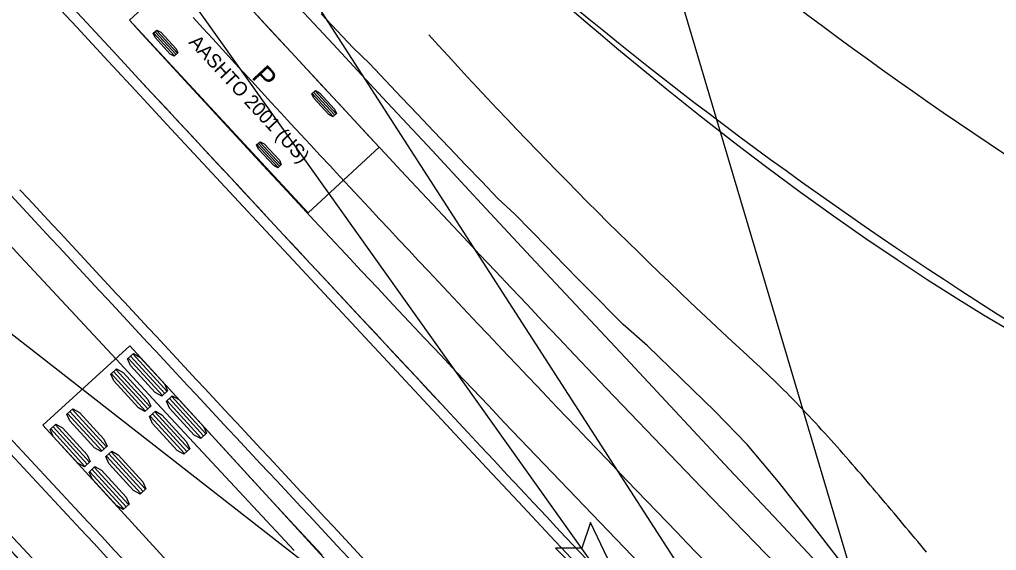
# Model space of a CAD drawing. Extents: x 1262642 to 1268358, y 767825 to 773481.
# Drawn here: x 1266689.1 to 1266759.8, y 772247.4 to 772285.8 of the extents above; entities that cross this region are included whole.
import ezdxf

# ---------------------------------------------------------------- set-up
doc = ezdxf.new("R2010")
doc.units = 0
for name, color, linetype in [('Prop Conc 1ft 6in Curb and Gutter', 7, 'Continuous'), ('Prop Conc 5in Monolithic Keyed In Island', 7, 'Continuous'), ('Prop Dimension Text', 7, 'Continuous'), ('Prop EOT', 7, 'Continuous'), ('Prop Horizontal Alignment', 7, 'Continuous'), ('Prop Lane Lines', 7, 'Continuous'), ('Prop Paved Shoulder', 7, 'Continuous'), ('Prop Shade Light', 7, 'Continuous'), ('Prop Shade Medium', 7, 'Continuous'), ('Prop Terminator CELL', 7, 'Continuous'), ('Scratch_Level_3', 7, 'Continuous')]:
    doc.layers.add(name, color=color, linetype=linetype)

msp = doc.modelspace()

# ---------------------------------------------------------------- linework, layer by layer
at = {"layer": 'Prop Conc 1ft 6in Curb and Gutter'}
for radius, start, end in [(11385.75, 220.9464115, 223.1036607), (11396.75, 222.8296601, 223.1041091)]:
    msp.add_arc((1275047.307, 780021.225), radius, start, end, dxfattribs=at)
at = {"layer": 'Prop Conc 5in Monolithic Keyed In Island'}
for radius, start, end in [(11410.25, 222.8296601, 223.2792706), (11414.25, 222.8297896, 223.4298287)]:
    msp.add_arc((1275047.307, 780021.225), radius, start, end, dxfattribs=at)
at = {"layer": 'Prop Dimension Text'}
for p, q in [((1266734.359, 772241.11), (1266654.367, 772353.573)), ((1266758.201, 772215.712), (1266729.837, 772311.282)), ((1266637.674, 772302.797), (1266726.388, 772233.528)), ((1266758.372, 772212.843), (1266700.467, 772302.683))]:
    msp.add_line(p, q, dxfattribs=at)
at = {"layer": 'Prop EOT'}
for centre, radius, start, end in [((1275047.307, 780021.225), 11385, 220.9464115, 222.9935866), ((1266920.515, 772517.827), 300, 222.71603, 239.6427), ((1275047.307, 780021.225), 11385, 222.8296601, 223.2789723), ((1275047.307, 780021.225), 11397.5, 222.8287756, 223.1041206), ((1275047.307, 780021.225), 11409.5, 222.8296601, 223.2792706), ((1275047.307, 780021.225), 11415, 222.8297896, 223.4298287)]:
    msp.add_arc(centre, radius, start, end, dxfattribs=at)
at = {"layer": 'Prop Horizontal Alignment'}
msp.add_arc((1275047.307, 780021.225), 11400, 216.7663646, 222.9935866, dxfattribs=at)
at = {"layer": 'Prop Lane Lines'}
for radius, start, end in [(11373, 216.3649439, 223.1327476), (11427, 216.3674993, 223.5476842), (11415, 220.9464115, 223.1041206)]:
    msp.add_arc((1275047.307, 780021.225), radius, start, end, dxfattribs=at)
at = {"layer": 'Prop Paved Shoulder'}
for centre, radius, start, end in [((1275047.307, 780021.225), 11449, 220.5050908, 223.2024475), ((1266920.515, 772517.827), 290, 222.71603, 239.65201)]:
    msp.add_arc(centre, radius, start, end, dxfattribs=at)
at = {"layer": 'Prop Shade Light'}
for centre, radius, start, end in [((1275047.307, 780021.225), 11449, 220.5050908, 223.2024475), ((1266920.515, 772517.827), 290, 222.71603, 239.65201), ((1266920.515, 772517.827), 300, 222.71603, 239.6427)]:
    msp.add_arc(centre, radius, start, end, dxfattribs=at)
at = {"layer": 'Prop Shade Medium'}
for radius, start, end in [(11410.25, 222.8296601, 223.2792706), (11414.25, 222.8297896, 223.4298287)]:
    msp.add_arc((1275047.307, 780021.225), radius, start, end, dxfattribs=at)
at = {"layer": 'Prop Terminator CELL'}
msp.add_lwpolyline([(1266727.879, 772247.545), (1266734.359, 772241.11), (1266730.417, 772249.412), (1266729.78, 772247.547)], close=True, dxfattribs=at)
at = {"layer": 'Scratch_Level_3'}
for p, q in [((1266702.231, 772290.506), (1266697.093, 772285.751)), ((1266715.136, 772276.561), (1266702.231, 772290.506)), ((1266697.093, 772285.751), (1266709.998, 772271.806)), ((1266697.093, 772285.751), (1266697.093, 772285.751)), ((1266698.84, 772284.816), (1266700.359, 772283.156)), ((1266698.944, 772284.911), (1266700.463, 772283.251)), ((1266699.048, 772285.006), (1266700.567, 772283.346)), ((1266710.299, 772280.43), (1266711.828, 772278.779)), ((1266710.403, 772280.526), (1266711.931, 772278.874)), ((1266710.506, 772280.621), (1266712.034, 772278.97)), ((1266706.412, 772276.832), (1266707.94, 772275.181)), ((1266706.515, 772276.928), (1266708.043, 772275.277)), ((1266706.309, 772276.737), (1266707.837, 772275.085)), ((1266709.998, 772271.806), (1266715.136, 772276.561)), ((1266697.109, 772262.181), (1266690.837, 772256.444)), ((1266729.506, 772226.762), (1266697.109, 772262.181)), ((1266699.639, 772258.735), (1266697.165, 772261.441)), ((1266699.808, 772258.89), (1266697.334, 772261.595)), ((1266699.47, 772258.581), (1266696.995, 772261.286)), ((1266698.253, 772257.467), (1266695.778, 772260.172)), ((1266698.422, 772257.622), (1266695.947, 772260.327)), ((1266698.591, 772257.776), (1266696.116, 772260.482)), ((1266702.621, 772255.815), (1266700.146, 772258.521)), ((1266702.282, 772255.506), (1266699.808, 772258.212)), ((1266702.451, 772255.661), (1266699.977, 772258.366)), ((1266695.092, 772254.576), (1266692.617, 772257.282)), ((1266695.261, 772254.731), (1266692.786, 772257.436)), ((1266695.43, 772254.885), (1266692.956, 772257.591)), ((1266701.065, 772254.392), (1266698.59, 772257.098)), ((1266701.234, 772254.547), (1266698.759, 772257.253)), ((1266701.403, 772254.702), (1266698.928, 772257.407)), ((1266690.837, 772256.444), (1266723.234, 772221.025)), ((1266694.213, 772253.772), (1266691.738, 772256.477)), ((1266693.875, 772253.462), (1266691.4, 772256.168)), ((1266694.044, 772253.617), (1266691.569, 772256.323)), ((1266698.073, 772251.656), (1266695.599, 772254.362)), ((1266698.243, 772251.811), (1266695.768, 772254.516)), ((1266697.904, 772251.501), (1266695.43, 772254.207)), ((1266696.687, 772250.388), (1266694.212, 772253.093)), ((1266696.856, 772250.543), (1266694.381, 772253.248)), ((1266697.025, 772250.697), (1266694.55, 772253.403))]:
    msp.add_line(p, q, dxfattribs=at)
for points in [[(1266728.117, 772262.745), (1266726.973, 772263.953), (1266725.829, 772265.163), (1266724.686, 772266.373), (1266723.544, 772267.585), (1266722.403, 772268.797), (1266721.263, 772270.011), (1266720.125, 772271.225), (1266718.987, 772272.441), (1266717.85, 772273.657), (1266716.715, 772274.874), (1266715.58, 772276.093), (1266714.446, 772277.312), (1266713.314, 772278.532), (1266712.182, 772279.753), (1266711.051, 772280.975), (1266709.92, 772282.197), (1266708.79, 772283.419), (1266707.659, 772284.641), (1266706.528, 772285.863), (1266705.397, 772287.084), (1266704.266, 772288.306), (1266703.136, 772289.528), (1266702.231, 772290.506)], [(1266741.475, 772276.359), (1266740.75, 772276.916), (1266739.543, 772277.855), (1266738.336, 772278.804), (1266737.131, 772279.764), (1266735.927, 772280.734), (1266734.725, 772281.714), (1266733.525, 772282.703), (1266732.326, 772283.702), (1266731.13, 772284.71), (1266729.93, 772285.73), (1266728.732, 772286.76)], [(1266732.788, 772263.728), (1266732.065, 772264.448), (1266730.865, 772265.651), (1266729.67, 772266.858), (1266728.481, 772268.069), (1266727.298, 772269.285), (1266726.12, 772270.502), (1266724.945, 772271.719), (1266723.723, 772272.841), (1266722.555, 772274.061), (1266721.389, 772275.281), (1266720.226, 772276.501), (1266719.065, 772277.72), (1266717.907, 772278.94), (1266716.75, 772280.159), (1266715.596, 772281.379), (1266714.444, 772282.6), (1266713.252, 772283.753), (1266712.103, 772284.978), (1266710.953, 772286.205)], [(1266723.035, 772257.856), (1266721.886, 772259.069), (1266720.738, 772260.283), (1266719.591, 772261.498), (1266718.446, 772262.714), (1266717.301, 772263.931), (1266716.157, 772265.149), (1266715.014, 772266.367), (1266713.872, 772267.587), (1266712.731, 772268.808), (1266711.591, 772270.03), (1266710.453, 772271.252), (1266709.315, 772272.476), (1266708.178, 772273.7), (1266707.043, 772274.926), (1266705.908, 772276.152), (1266704.774, 772277.38), (1266703.642, 772278.608), (1266702.51, 772279.837), (1266701.38, 772281.068), (1266700.25, 772282.299), (1266699.122, 772283.531), (1266697.995, 772284.764), (1266697.093, 772285.751)], [(1266754.753, 772266.958), (1266752.569, 772268.393), (1266750.306, 772269.927), (1266747.972, 772271.56), (1266745.585, 772273.281), (1266743.167, 772275.074), (1266741.475, 772276.359)], [(1266798.144, 772250.227), (1266795.159, 772250.511), (1266792.263, 772250.936), (1266789.482, 772251.473), (1266786.847, 772252.093), (1266784.374, 772252.768), (1266782.045, 772253.484), (1266779.866, 772254.221), (1266777.761, 772254.994), (1266775.715, 772255.801), (1266773.727, 772256.636), (1266771.794, 772257.496), (1266769.914, 772258.377), (1266768.085, 772259.275), (1266766.289, 772260.195), (1266764.484, 772261.159), (1266762.632, 772262.184), (1266760.749, 772263.266), (1266758.826, 772264.41), (1266756.843, 772265.63), (1266754.753, 772266.958)], [(1266746.21, 772249.534), (1266743.993, 772252.338), (1266741.748, 772255.044), (1266739.397, 772257.468), (1266736.972, 772259.812), (1266734.532, 772262.182), (1266732.788, 772263.728)], [(1266760.466, 772229.481), (1266758.549, 772231.381), (1266756.544, 772233.398), (1266754.451, 772235.514), (1266752.278, 772237.719), (1266750.036, 772240.002), (1266747.735, 772242.353), (1266745.412, 772244.736), (1266743.093, 772247.124), (1266740.778, 772249.516), (1266738.467, 772251.912), (1266736.16, 772254.312), (1266733.857, 772256.716), (1266731.558, 772259.125), (1266729.263, 772261.537), (1266728.117, 772262.745)], [(1266697.109, 772262.181), (1266699.423, 772259.651), (1266701.737, 772257.121), (1266704.052, 772254.592), (1266706.37, 772252.066), (1266708.695, 772249.546), (1266711.029, 772247.034)], [(1266754.707, 772247.254), (1266754.494, 772247.51), (1266754.28, 772247.766), (1266754.067, 772248.022), (1266753.853, 772248.278), (1266753.64, 772248.534), (1266753.426, 772248.79), (1266753.213, 772249.046), (1266752.999, 772249.302), (1266752.786, 772249.558), (1266752.572, 772249.814), (1266752.358, 772250.069), (1266752.144, 772250.325), (1266751.93, 772250.58), (1266751.715, 772250.836), (1266751.501, 772251.091), (1266751.286, 772251.346), (1266751.071, 772251.6), (1266750.855, 772251.854), (1266750.639, 772252.109), (1266750.423, 772252.362), (1266750.207, 772252.616), (1266749.99, 772252.869), (1266749.772, 772253.121), (1266749.554, 772253.374), (1266749.336, 772253.625), (1266749.117, 772253.877), (1266748.898, 772254.128), (1266748.678, 772254.378), (1266748.457, 772254.628), (1266748.236, 772254.877), (1266748.014, 772255.126), (1266747.792, 772255.374), (1266747.568, 772255.622), (1266747.345, 772255.869), (1266747.12, 772256.115), (1266746.895, 772256.361), (1266746.668, 772256.606), (1266746.441, 772256.85), (1266746.214, 772257.093), (1266745.985, 772257.336), (1266745.755, 772257.577), (1266745.525, 772257.818), (1266745.294, 772258.058), (1266745.061, 772258.297), (1266744.828, 772258.535), (1266744.594, 772258.773), (1266744.359, 772259.009), (1266744.122, 772259.244), (1266743.885, 772259.478), (1266743.647, 772259.711), (1266743.407, 772259.943), (1266743.166, 772260.173), (1266742.925, 772260.403), (1266742.682, 772260.631), (1266742.438, 772260.858), (1266742.193, 772261.084)], [(1266761.603, 772214.984), (1266758.62, 772217.483), (1266755.997, 772220.375), (1266753.614, 772223.372), (1266751.395, 772226.376), (1266749.266, 772229.328), (1266747.155, 772232.178), (1266744.994, 772234.878), (1266742.725, 772237.376), (1266740.393, 772239.772), (1266738.065, 772242.171), (1266735.742, 772244.574), (1266733.422, 772246.981), (1266731.107, 772249.391), (1266728.796, 772251.805), (1266726.489, 772254.222), (1266724.185, 772256.644), (1266723.035, 772257.856)], [(1266690.837, 772256.444), (1266693.151, 772253.913), (1266695.463, 772251.382), (1266697.776, 772248.851), (1266700.092, 772246.323), (1266702.407, 772243.794), (1266704.721, 772241.264), (1266707.035, 772238.735), (1266709.349, 772236.205), (1266711.664, 772233.675), (1266713.978, 772231.145), (1266716.292, 772228.615), (1266718.606, 772226.085), (1266720.92, 772223.555), (1266723.234, 772221.025), (1266723.234, 772221.025), (1266725.546, 772218.51), (1266727.888, 772216.021), (1266730.244, 772213.547), (1266732.581, 772211.054), (1266734.918, 772208.561), (1266737.254, 772206.068), (1266737.254, 772206.068), (1266739.603, 772203.675)], [(1266796.344, 772224.878), (1266792.813, 772224.356), (1266789.186, 772224.25), (1266785.516, 772224.574), (1266781.868, 772225.177), (1266778.27, 772226.026), (1266774.738, 772227.117), (1266771.287, 772228.446), (1266767.935, 772230.007), (1266764.697, 772231.792), (1266761.587, 772233.794), (1266758.621, 772236.002), (1266755.811, 772238.406), (1266753.171, 772240.996), (1266750.714, 772243.76), (1266748.433, 772246.659), (1266746.21, 772249.534)]]:
    msp.add_lwpolyline(points, dxfattribs=at)
for points in [[(1266698.815, 772284.793), (1266699.073, 772285.03), (1266699.364, 772284.869), (1266700.458, 772283.674), (1266700.592, 772283.37), (1266700.333, 772283.133), (1266700.043, 772283.294), (1266698.949, 772284.489)], [(1266710.274, 772280.406), (1266710.531, 772280.645), (1266710.823, 772280.485), (1266711.923, 772279.296), (1266712.06, 772278.993), (1266711.802, 772278.755), (1266711.51, 772278.914), (1266710.41, 772280.103)], [(1266706.283, 772276.713), (1266706.541, 772276.952), (1266706.832, 772276.792), (1266707.932, 772275.603), (1266708.069, 772275.3), (1266707.811, 772275.062), (1266707.52, 772275.221), (1266706.419, 772276.41)], [(1266699.85, 772258.928), (1266699.428, 772258.542), (1266698.955, 772258.805), (1266697.173, 772260.753), (1266696.953, 772261.248), (1266697.376, 772261.634), (1266697.849, 772261.371), (1266699.631, 772259.423)], [(1266698.633, 772257.815), (1266698.211, 772257.429), (1266697.737, 772257.691), (1266695.955, 772259.639), (1266695.736, 772260.134), (1266696.158, 772260.52), (1266696.632, 772260.258), (1266698.413, 772258.31)], [(1266702.663, 772255.854), (1266702.24, 772255.468), (1266701.767, 772255.73), (1266699.985, 772257.678), (1266699.766, 772258.173), (1266700.188, 772258.559), (1266700.661, 772258.297), (1266702.443, 772256.349)], [(1266695.472, 772254.924), (1266695.05, 772254.538), (1266694.577, 772254.8), (1266692.795, 772256.748), (1266692.575, 772257.243), (1266692.997, 772257.629), (1266693.471, 772257.367), (1266695.253, 772255.419)], [(1266701.445, 772254.74), (1266701.023, 772254.354), (1266700.549, 772254.617), (1266698.768, 772256.565), (1266698.548, 772257.06), (1266698.97, 772257.446), (1266699.444, 772257.183), (1266701.226, 772255.235)], [(1266694.255, 772253.81), (1266693.833, 772253.424), (1266693.359, 772253.686), (1266691.577, 772255.634), (1266691.358, 772256.13), (1266691.78, 772256.516), (1266692.254, 772256.253), (1266694.035, 772254.305)], [(1266698.284, 772251.849), (1266697.862, 772251.463), (1266697.389, 772251.726), (1266695.607, 772253.674), (1266695.388, 772254.169), (1266695.81, 772254.555), (1266696.283, 772254.292), (1266698.065, 772252.344)], [(1266697.067, 772250.736), (1266696.645, 772250.349), (1266696.171, 772250.612), (1266694.389, 772252.56), (1266694.17, 772253.055), (1266694.592, 772253.441), (1266695.066, 772253.179), (1266696.848, 772251.231)]]:
    msp.add_lwpolyline(points, close=True, dxfattribs=at)
for centre, radius, start, end in [((1268163.048, 773623.07), 1980.781, 222.458728, 224.388454), ((1266982.142, 772523.106), 355.291, 222.14745, 227.51783)]:
    msp.add_arc(centre, radius, start, end, dxfattribs=at)

# ---------------------------------------------------------------- texts
at = {"layer": 'Prop Dimension Text'}
for s, p in [('-Y38NE- +04.43', (1266795.378, 772285.545)), ('-Y38NE- +84.08', (1266785.276, 772272.357))]:
    msp.add_text(s, height=5, rotation=135.42387, dxfattribs=at).set_placement(p)
at = {"layer": 'Scratch_Level_3'}
for s, height, p in [('AASHTO 2001 (US)', 1, (1266701.335, 772284.105)), ('P', 1.5, (1266705.863, 772281.605)), ('(c) 2016 Transoft Solutions, Inc. All rights reserved.', 0.06, (1266705.262, 772282.033))]:
    msp.add_text(s, height=height, rotation=312.78203, dxfattribs=at).set_placement(p)

doc.saveas('drawing.dxf')
